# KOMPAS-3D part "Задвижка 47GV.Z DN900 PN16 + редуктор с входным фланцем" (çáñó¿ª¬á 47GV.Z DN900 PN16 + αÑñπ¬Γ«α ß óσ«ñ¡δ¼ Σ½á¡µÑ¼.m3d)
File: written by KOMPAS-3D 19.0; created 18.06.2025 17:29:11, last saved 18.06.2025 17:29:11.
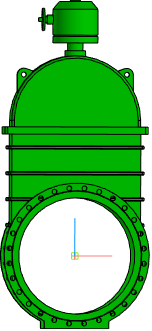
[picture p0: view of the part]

Document properties: Полное имя файла: Задвижка 47GV.Z DN900 PN16 + редуктор с входным валом.a3d

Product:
- Part/product: Задвижка 47GV.Z DN900 PN16 + редуктор с входным фланцем
    Масса: 3557.18
  - Body: Тело 1
      Масса: 3559.37

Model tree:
1. Операция без истории:1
